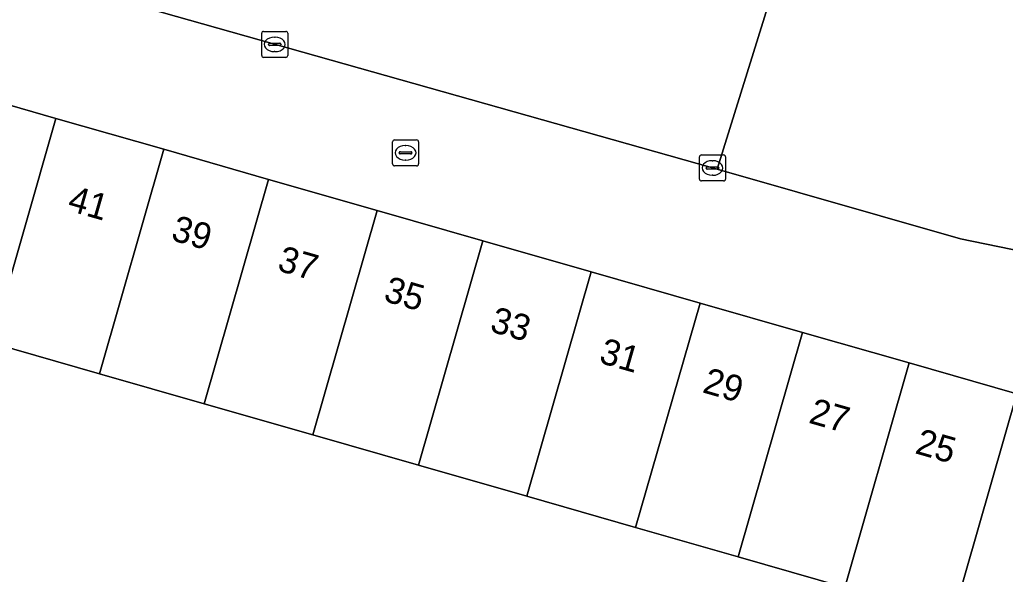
# Model space of a CAD drawing. Extents: x 158086 to 159499, y 382904 to 383981.
# Drawn here: x 158859.59 to 158897.48, y 383342.27 to 383363.6 of the extents above; entities that cross this region are included whole.
import ezdxf

# ---------------------------------------------------------------- set-up
doc = ezdxf.new("R2010")
doc.units = 0
for name, color, linetype in [('IMGEO_Brandkraan', 7, 'Continuous'), ('IMGEO_Erf', 7, 'Continuous'), ('IMGEO_Kolk', 7, 'Continuous'), ('IMGEO_Pand', 7, 'Continuous'), ('IMGEO_Pand_nummerreeks', 7, 'Continuous'), ('IMGEO_Rijbaan_lokaal_open', 7, 'Continuous'), ('IMGEO_Voetpad_open', 7, 'Continuous')]:
    doc.layers.add(name, color=color, linetype=linetype)

msp = doc.modelspace()

# ---------------------------------------------------------------- linework, layer by layer
at = {"layer": 'IMGEO_Brandkraan'}
for p, q in [((158873.924, 383358.054), (158873.924, 383358.906)), ((158873.999, 383358.98), (158874.851, 383358.98)), ((158874.925, 383358.906), (158874.925, 383358.054)), ((158874.183, 383358.474), (158874.183, 383358.486)), ((158874.226, 383358.523), (158874.624, 383358.523)), ((158874.412, 383358.76), (158874.437, 383358.76)), ((158874.667, 383358.486), (158874.667, 383358.474)), ((158874.621, 383358.437), (158874.223, 383358.437)), ((158874.435, 383358.2), (158874.41, 383358.2)), ((158874.851, 383357.98), (158873.999, 383357.98))]:
    msp.add_line(p, q, dxfattribs=at)
for points in [[(158873.924, 383358.054), (158873.924, 383358.906)], [(158873.999, 383358.98), (158874.851, 383358.98)], [(158874.925, 383358.906), (158874.925, 383358.054)], [(158874.851, 383357.98), (158873.999, 383357.98)]]:
    msp.add_lwpolyline(points, dxfattribs=at)
for centre, radius, start, end in [((158874.001, 383358.904), 0.0765, 91.552, 178.448), ((158874.001, 383358.904), 0.0765, 91.552, 178.448), ((158874.849, 383358.904), 0.0765, 1.552, 88.448), ((158874.849, 383358.904), 0.0765, 1.552, 88.448), ((158874.223, 383358.483), 0.0403, 85.8775, 175.7526), ((158874.628, 383358.485), 0.0386, 1.7309, 96.639), ((158874.22, 383358.473), 0.0366, 178.938, 274.7102), ((158874.624, 383358.48), 0.043, 264.8664, 352.4533), ((158874.001, 383358.056), 0.0765, 181.552, 268.448), ((158874.001, 383358.056), 0.0765, 181.552, 268.448), ((158874.849, 383358.056), 0.0765, 271.552, 358.448), ((158874.849, 383358.056), 0.0765, 271.552, 358.448)]:
    msp.add_arc(centre, radius, start, end, dxfattribs=at)
for centre, major_axis, ratio, start_param, end_param in [((158874.411, 383358.48), (-0.387, 0.002), 0.722429, 4.712389, 7.853982), ((158874.436, 383358.48), (-0.39, 0.002), 0.717154, 1.570796, 4.712389)]:
    msp.add_ellipse(centre, major_axis=major_axis, ratio=ratio, start_param=start_param, end_param=end_param, dxfattribs=at)
at = {"layer": 'IMGEO_Erf'}
msp.add_lwpolyline([(158891.304, 383341.767), (158887.207, 383342.942), (158883.269, 383344.072), (158879.085, 383345.272), (158874.921, 383346.466), (158870.863, 383347.63), (158866.686, 383348.828), (158862.654, 383349.984), (158858.512, 383351.172), (158858.03, 383349.492), (158853.932, 383350.629), (158854.409, 383352.349), (158855.473, 383356.184), (158856.851, 383360.99), (158854.691, 383361.606), (158850.158, 383345.722), (158848.607, 383340.176)], dxfattribs=at)
at = {"layer": 'IMGEO_Kolk'}
for p, q in [((158868.894, 383362.226), (158868.894, 383363.078)), ((158868.969, 383363.152), (158869.821, 383363.152)), ((158869.895, 383363.078), (158869.895, 383362.226)), ((158869.153, 383362.646), (158869.153, 383362.658)), ((158869.196, 383362.695), (158869.594, 383362.695)), ((158869.382, 383362.932), (158869.407, 383362.932)), ((158869.637, 383362.658), (158869.637, 383362.646)), ((158869.591, 383362.609), (158869.193, 383362.609)), ((158869.405, 383362.372), (158869.38, 383362.372)), ((158869.821, 383362.152), (158868.969, 383362.152)), ((158885.722, 383357.472), (158885.722, 383358.324)), ((158885.797, 383358.398), (158886.649, 383358.398)), ((158886.21, 383358.178), (158886.235, 383358.178)), ((158886.723, 383358.324), (158886.723, 383357.472)), ((158885.981, 383357.892), (158885.981, 383357.904)), ((158886.419, 383357.855), (158886.021, 383357.855)), ((158886.024, 383357.941), (158886.422, 383357.941)), ((158886.465, 383357.904), (158886.465, 383357.892)), ((158886.649, 383357.398), (158885.797, 383357.398)), ((158886.233, 383357.618), (158886.208, 383357.618))]:
    msp.add_line(p, q, dxfattribs=at)
for points in [[(158868.894, 383362.226), (158868.894, 383363.078)], [(158868.969, 383363.152), (158869.821, 383363.152)], [(158869.895, 383363.078), (158869.895, 383362.226)], [(158869.821, 383362.152), (158868.969, 383362.152)], [(158885.722, 383357.472), (158885.722, 383358.324)], [(158885.797, 383358.398), (158886.649, 383358.398)], [(158886.723, 383358.324), (158886.723, 383357.472)], [(158886.649, 383357.398), (158885.797, 383357.398)]]:
    msp.add_lwpolyline(points, dxfattribs=at)
for centre, radius, start, end in [((158868.971, 383363.076), 0.0765, 91.552, 178.448), ((158868.971, 383363.076), 0.0765, 91.552, 178.448), ((158869.819, 383363.076), 0.0765, 1.552, 88.448), ((158869.819, 383363.076), 0.0765, 1.552, 88.448), ((158869.193, 383362.655), 0.0403, 85.8775, 175.7526), ((158869.598, 383362.657), 0.0386, 1.7309, 96.639), ((158869.19, 383362.645), 0.0366, 178.938, 274.7102), ((158869.594, 383362.652), 0.043, 264.8664, 352.4533), ((158868.971, 383362.228), 0.0765, 181.552, 268.448), ((158868.971, 383362.228), 0.0765, 181.552, 268.448), ((158869.819, 383362.228), 0.0765, 271.552, 358.448), ((158869.819, 383362.228), 0.0765, 271.552, 358.448), ((158885.799, 383358.322), 0.0765, 91.552, 178.448), ((158885.799, 383358.322), 0.0765, 91.552, 178.448), ((158886.647, 383358.322), 0.0765, 1.552, 88.448), ((158886.647, 383358.322), 0.0765, 1.552, 88.448), ((158886.021, 383357.901), 0.0403, 85.8775, 175.7526), ((158886.018, 383357.891), 0.0366, 178.938, 274.7102), ((158886.422, 383357.898), 0.043, 264.8664, 352.4533), ((158886.426, 383357.903), 0.0386, 1.7309, 96.639), ((158885.799, 383357.474), 0.0765, 181.552, 268.448), ((158885.799, 383357.474), 0.0765, 181.552, 268.448), ((158886.647, 383357.474), 0.0765, 271.552, 358.448), ((158886.647, 383357.474), 0.0765, 271.552, 358.448)]:
    msp.add_arc(centre, radius, start, end, dxfattribs=at)
for centre, major_axis, ratio, start_param, end_param in [((158869.381, 383362.652), (-0.387, 0.002), 0.722429, 4.712389, 7.853982), ((158869.406, 383362.652), (-0.39, 0.002), 0.717154, 1.570796, 4.712389), ((158886.209, 383357.898), (-0.387, 0.002), 0.722429, 4.712389, 7.853982), ((158886.234, 383357.898), (-0.39, 0.002), 0.717154, 1.570796, 4.712389)]:
    msp.add_ellipse(centre, major_axis=major_axis, ratio=ratio, start_param=start_param, end_param=end_param, dxfattribs=at)
at = {"layer": 'IMGEO_Pand'}
for points in [[(158860.988, 383359.804), (158856.851, 383360.99), (158855.473, 383356.184), (158854.409, 383352.349), (158853.932, 383350.629), (158858.03, 383349.492), (158858.512, 383351.172)], [(158862.654, 383349.984), (158865.129, 383358.616), (158860.988, 383359.804), (158858.512, 383351.172)], [(158862.654, 383349.984), (158866.686, 383348.828), (158869.161, 383357.46), (158865.129, 383358.616)], [(158870.863, 383347.63), (158873.339, 383356.262), (158869.161, 383357.46), (158866.686, 383348.828)], [(158870.863, 383347.63), (158874.921, 383346.466), (158877.397, 383355.099), (158873.339, 383356.262)], [(158881.561, 383353.905), (158877.397, 383355.099), (158874.921, 383346.466), (158879.085, 383345.272)], [(158881.561, 383353.905), (158879.085, 383345.272), (158883.269, 383344.072), (158885.745, 383352.705)], [(158887.207, 383342.942), (158889.682, 383351.576), (158885.745, 383352.705), (158883.269, 383344.072)], [(158887.207, 383342.942), (158891.304, 383341.767), (158893.78, 383350.401), (158889.682, 383351.576)], [(158897.922, 383349.213), (158893.78, 383350.401), (158891.304, 383341.767), (158895.446, 383340.579)], [(158901.882, 383348.078), (158897.922, 383349.213), (158895.446, 383340.579), (158894.947, 383338.837), (158898.772, 383337.74), (158899.272, 383339.481), (158899.405, 383339.443)]]:
    msp.add_lwpolyline(points, close=True, dxfattribs=at)
at = {"layer": 'IMGEO_Rijbaan_lokaal_open'}
msp.add_lwpolyline([(158886.403, 383357.857), (158888.47, 383364.499), (158887.011, 383364.933), (158883.863, 383365.795), (158850.696, 383375.212), (158839.319, 383378.442), (158832.46, 383380.397), (158830.515, 383373.709), (158830.616, 383373.672), (158836.657, 383371.953), (158848.856, 383368.492), (158851.376, 383367.777), (158854.716, 383366.83), (158855.909, 383366.491), (158859.089, 383365.589), (158880.188, 383359.604), (158886.223, 383357.899)], close=True, dxfattribs=at)
msp.add_lwpolyline([(158889.178, 383364.324), (158888.47, 383364.499), (158886.403, 383357.857), (158895.754, 383355.173), (158898.685, 383354.576)], dxfattribs=at)
at = {"layer": 'IMGEO_Voetpad_open'}
for points in [[(158898.685, 383354.576), (158895.754, 383355.173), (158886.403, 383357.857), (158886.223, 383357.899), (158880.188, 383359.604), (158859.089, 383365.589), (158858.805, 383364.588), (158855.625, 383365.49), (158855.909, 383366.491), (158854.716, 383366.83), (158854.432, 383365.829), (158851.092, 383366.776), (158851.376, 383367.777), (158848.856, 383368.492), (158836.657, 383371.953), (158830.616, 383373.672), (158830.515, 383373.709), (158811.299, 383379.137), (158810.816, 383379.277), (158803.832, 383381.26), (158764.081, 383392.596), (158757.401, 383394.452), (158756.229, 383394.782), (158753.608, 383395.531)], [(158856.851, 383360.99), (158860.988, 383359.804), (158865.129, 383358.616), (158869.161, 383357.46), (158873.339, 383356.262), (158877.397, 383355.099), (158881.561, 383353.905), (158885.745, 383352.705), (158889.682, 383351.576), (158893.78, 383350.401), (158897.922, 383349.213)]]:
    msp.add_lwpolyline(points, dxfattribs=at)

# ---------------------------------------------------------------- texts
at = {"layer": 'IMGEO_Pand_nummerreeks'}
for s, rotation, p in [('41', 344.0001, (158861.389, 383356.277)), ('39', 344.0001, (158865.367, 383355.136)), ('37', 344.0001, (158869.453, 383353.965)), ('35', 344.0001, (158873.539, 383352.793)), ('33', 344.0001, (158877.625, 383351.622)), ('31', 344.0001, (158881.819, 383350.419)), ('29', 344.0001, (158885.796, 383349.278)), ('27', 344.0001, (158889.882, 383348.107)), ('25', 343.9973, (158893.968, 383346.935))]:
    msp.add_text(s, height=1, rotation=rotation, dxfattribs=at).set_placement(p)

doc.saveas('drawing.dxf')
